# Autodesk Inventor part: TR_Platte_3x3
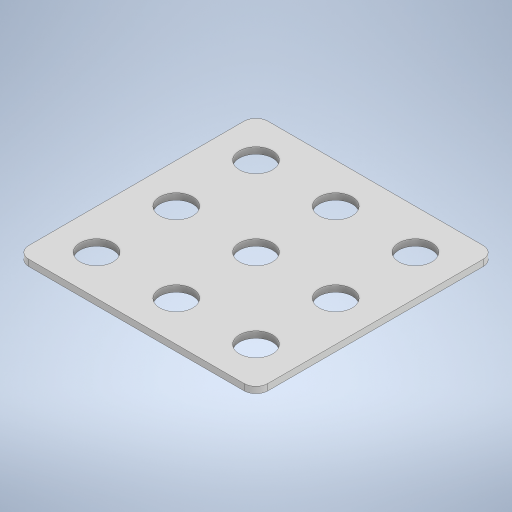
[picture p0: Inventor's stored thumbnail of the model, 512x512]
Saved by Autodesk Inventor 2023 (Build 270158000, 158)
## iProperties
Created: 2023-11
Part Number: TR_Platte_3x3
Material: Generisch
Document SubType Name: Modeling
Designer: Administrator
Density: 1 g/cm^3
Appearance: Vorgabe
Author: Administrator
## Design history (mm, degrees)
sketch "Skizze1"
  geometry: L1 (15, 15)-(-15, 15); L2 (-15, 15)-(-15, -15); L3 (-15, -15)-(15, -15); L4 (15, -15)-(15, 15); L5 (15, 15)-(-15, -15); L6 (-15, 15)-(15, -15); 1 further point
  constraints: 12 end point, 2 midpoint, 2 parallel, 1 horizontal, 1 perpendicular
  dimensions: "d0" = 30 distance of L3.end L2.end (computed from Lochx, Einheitsmaß); "d1" = 30 distance of L3.end L1.start (computed from Lochy, Einheitsmaß)
extrude "Extrusion1" new body sketch "Skizze1" distance "d2" = 0.8 (= Dicke); taper "d3" = 0 deg
sketch "Skizze2"
  geometry: L1 (15, -15)-(15, 15) reference; L2 (-15, -15)-(15, -15) reference; C1 r 2.075 at (10, -10); 1 further point
  constraints: 1 centre point
  dimensions: "d4" = 4.15 diameter of C1 (= 2 x Radius); "d5" = 5 distance from line of L1 C1.centre (= 0.5 x Einheitsmaß); "d6" = 5 distance from line of C1.centre L2 (= 0.5 x Einheitsmaß)
extrude "Extrusion2" cut sketch "Skizze2" extent not by distance; stored distance "d7" = 0; taper "d8" = 0 deg
pattern_linear "Rechteckige Anordnung1" dims "d11" = 10 (= Einheitsmaß), "d14" = 10 (= Einheitsmaß)
fillet "Rundung1" dims "d15" = 1.5
node "Volumenkörper1"
other parameters: "Einheitsmaß" = 10 [user parameter; used in 6 equation terms], "Radius" = 2.075 [user parameter; used in 1 equation term], "Fasen" = 0.5 [user parameter], "Dicke" = 0.8 [user parameter; used in 1 equation term], "Breitloch" = 2 [user parameter], "Langloch" = 32 [user parameter], "AchteckUmkreis" = 6 [user parameter], "DAchsAufnahme" = 4.1 [user parameter], "AchsDurchmesser" = 4 [user parameter], "AchsFase" = 0.5 [user parameter]
